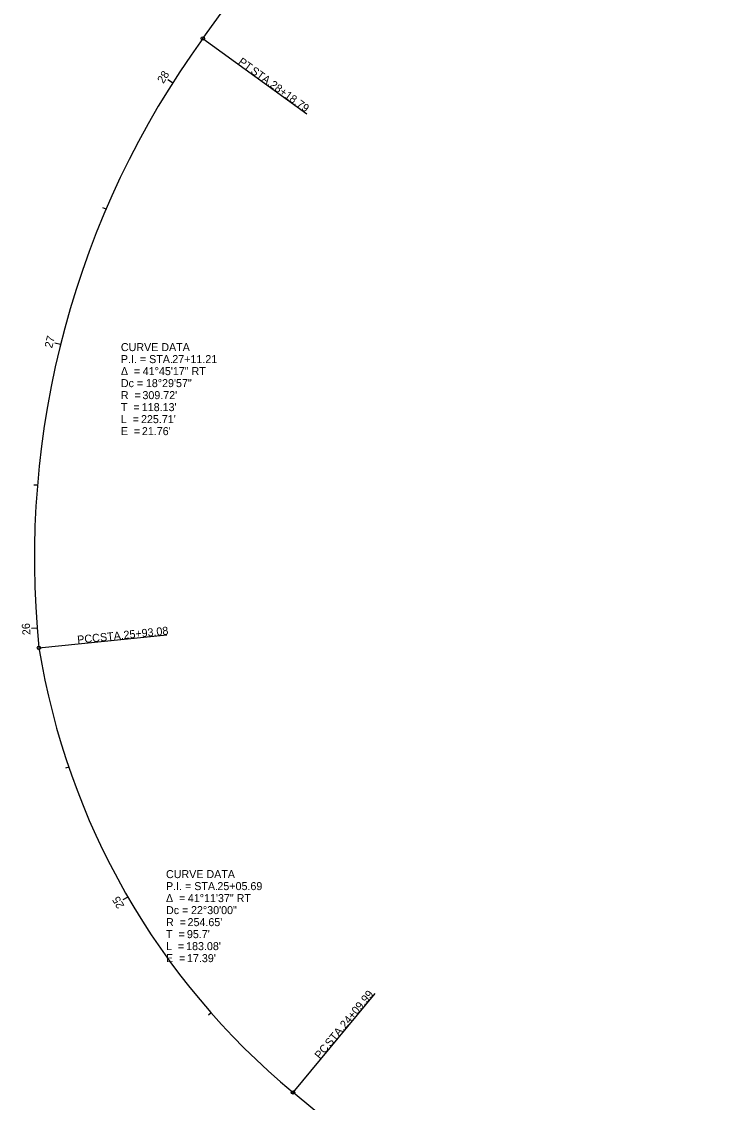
# Model space of a CAD drawing. Extents: x 127563 to 127989, y 300983 to 302508.
# Drawn here: x 127562.7 to 127803.4, y 301353.2 to 301731.3 of the extents above; entities that cross this region are included whole.
import ezdxf

# ---------------------------------------------------------------- set-up
doc = ezdxf.new("R2010")
doc.units = 0
for name, color, linetype in [('GK_Drainage_Nodes', 7, 'Continuous'), ('SC_Scratch1', 7, 'Continuous'), ('SV_X_Mon_Cells_Found', 7, 'Continuous'), ('SV_X_Shot_Marker', 7, 'Continuous')]:
    doc.layers.add(name, color=color, linetype=linetype)

msp = doc.modelspace()

# ---------------------------------------------------------------- linework, layer by layer
at = {"layer": 'GK_Drainage_Nodes'}
for p, q in [((127615.58, 301709.9), (127613.89, 301710.97)), ((127592.26, 301665.73), (127591.15, 301666.2)), ((127576.34, 301618.39), (127574.4, 301618.87)), ((127568.24, 301569.1), (127567.05, 301569.2)), ((127568.17, 301519.16), (127566.18, 301519)), ((127579.21, 301470.52), (127578.07, 301470.13)), ((127599.89, 301425.08), (127598.16, 301424.08)), ((127629.04, 301384.56), (127628.14, 301383.76))]:
    msp.add_line(p, q, dxfattribs=at)
at = {"layer": 'SC_Scratch1'}
for p, q in [((127626.13, 301725.43), (127662.57, 301699.03)), ((127568.79, 301512.26), (127613.56, 301516.83)), ((127657.71, 301356.72), (127686.43, 301391.37))]:
    msp.add_line(p, q, dxfattribs=at)
for centre in [(127626.13, 301725.43), (127568.79, 301512.26), (127657.71, 301356.72)]:
    msp.add_circle(centre, 0.6, dxfattribs=at)
at = {"layer": 'SV_X_Shot_Marker'}
for p, q in [((127626.13, 301725.43), (127659.09, 301770.91)), ((127803.43, 301235.96), (127657.71, 301356.72))]:
    msp.add_line(p, q, dxfattribs=at)
for centre, radius, start, end in [((127876.92, 301543.68), 309.72, 144.0676, 185.8223), ((127820.2, 301552.79), 254.65, 189.1579, 230.3515)]:
    msp.add_arc(centre, radius, start, end, dxfattribs=at)

# ---------------------------------------------------------------- texts
at = {"layer": 'GK_Drainage_Nodes'}
for s, rotation, p in [('28', 57.5433, (127612.32, 301709.44)), ('27', 76.0426, (127573.4, 301616.93)), ('26', 94.5418, (127565.85, 301516.83)), ('25', 120.1004, (127598.77, 301422.02))]:
    msp.add_text(s, height=2.8, rotation=rotation, dxfattribs=at).set_placement(p)
at = {"layer": 'SC_Scratch1'}
for s, rotation, p in [('PT', 324.0676, (127638.26, 301716.69)), (' STA. ', 324.0676, (127641.78, 301714.14)), ('28+18.79', 324.0676, (127649.33, 301708.67)), (' STA. ', 5.8223, (127589.26, 301514.39)), ('25+93.08', 5.8223, (127598.54, 301515.33)), ('PCC', 5.8223, (127582.34, 301513.68)), ('24+09.99', 50.3515, (127676.03, 301378.88)), (' STA. ', 50.3515, (127670.08, 301371.7)), ('PC', 50.3515, (127667.14, 301368.16))]:
    msp.add_text(s, height=2.8, rotation=rotation, dxfattribs=at).set_placement(p)
at = {"layer": 'SV_X_Mon_Cells_Found'}
for s, p in [('CURVE DATA', (127597.46, 301616.05)), ('P.I. = STA. ', (127597.46, 301611.85)), ('27+11.21', (127615.45, 301611.85)), ('Δ  = ', (127597.46, 301607.65)), ('41°45\'17" RT', (127605.11, 301607.65)), ('Dc = ', (127597.46, 301603.45)), ('18°29\'57"', (127606.21, 301603.45)), ('R  = ', (127597.46, 301599.25)), ("309.72'", (127605, 301599.25)), ('T  = ', (127597.46, 301595.05)), ("118.13'", (127604.78, 301595.05)), ('L  = ', (127597.46, 301590.85)), ("225.71'", (127604.5, 301590.85)), ('E  = ', (127597.46, 301586.65)), ("21.76'", (127604.81, 301586.65)), ('CURVE DATA', (127613.25, 301431.69)), ('P.I. = STA. ', (127613.25, 301427.49)), ('25+05.69', (127631.24, 301427.49)), ('Δ  = ', (127613.25, 301423.29)), ('41°11\'37" RT', (127620.9, 301423.29)), ('Dc = ', (127613.25, 301419.09)), ('22°30\'00"', (127622, 301419.09)), ('R  = ', (127613.25, 301414.89)), ("254.65'", (127620.79, 301414.89)), ('T  = ', (127613.25, 301410.69)), ("95.7'", (127620.57, 301410.69)), ('L  = ', (127613.25, 301406.49)), ("183.08'", (127620.29, 301406.49)), ('E  = ', (127613.25, 301402.29)), ("17.39'", (127620.6, 301402.29))]:
    msp.add_text(s, height=2.8, dxfattribs=at).set_placement(p)

doc.saveas('drawing.dxf')
